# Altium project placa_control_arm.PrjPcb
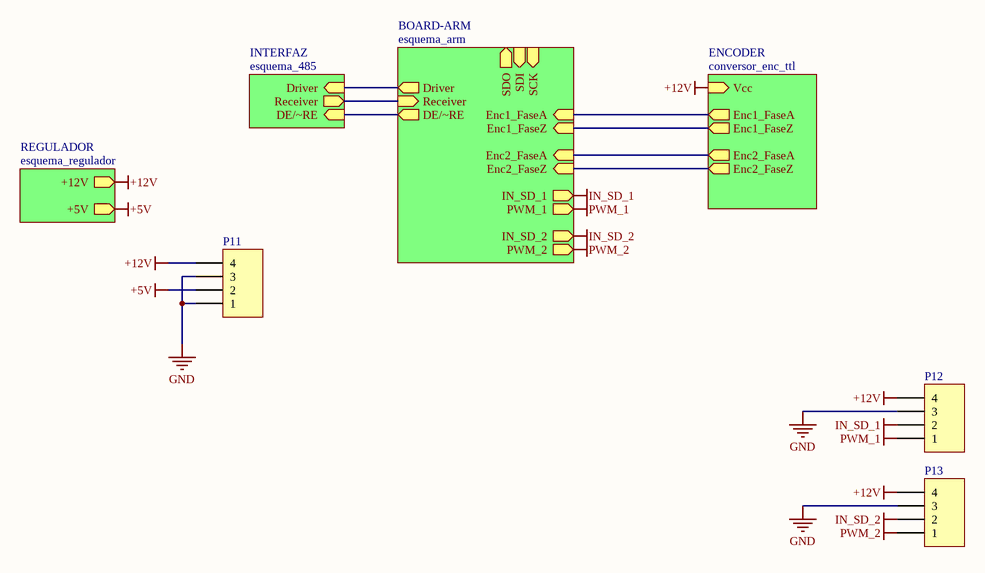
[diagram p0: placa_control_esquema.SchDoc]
5 sheets, 40 parts. Net scope: hierarchical (ports join the sheet entries above them; power ports are global).
Board file: placa_control_impresion.PcbDoc
Sheets:
  placa_control_esquema.SchDoc
    REGULADOR = esquema_regulador.SchDoc
    INTERFAZ = esquema_485.SchDoc
    BOARD-ARM = esquema_arm.SchDoc
    ENCODER = conversor_enc_ttl.SchDoc

## Sheet placa_control_esquema.SchDoc
size A4

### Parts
P11  Header 4  [HDR1X5]  (value not drawn)
P12  Header 4  [HDR1X5]  (value not drawn)
P13  Header 4  [HDR1X5]  (value not drawn)

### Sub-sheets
BOARD-ARM = esquema_arm: SDI (in), SDO (out), SCK (in), Enc1_FaseA (in), Enc1_FaseZ (in), Enc2_FaseA (in), Enc2_FaseZ (in), DE/~RE (out), Receiver (in), Driver (out), PWM_1 (out), PWM_2 (out), IN_SD_2 (out), IN_SD_1 (out)
ENCODER = conversor_enc_ttl: Enc1_FaseA (out), Enc1_FaseZ (out), Enc2_FaseA (out), Enc2_FaseZ (out), Vcc (in)
INTERFAZ = esquema_485: Driver (in), Receiver (out), DE/~RE (in)
REGULADOR = esquema_regulador: +12V (out), +5V (out)

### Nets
+5V: P11.2 ; sheet REGULADOR/+5V
+12V: P11.4 P12.4 P13.4 ; sheet REGULADOR/+12V, sheet ENCODER/Vcc
Enc1_FaseZ: sheet BOARD-ARM/Enc1_FaseZ, sheet ENCODER/Enc1_FaseZ
Enc2_FaseZ: sheet BOARD-ARM/Enc2_FaseZ, sheet ENCODER/Enc2_FaseZ
GND: P11.1 P11.3 P12.3 P13.3
IN_SD_1: P12.2 ; sheet BOARD-ARM/IN_SD_1
IN_SD_2: P13.2 ; sheet BOARD-ARM/IN_SD_2
PWM_1: P12.1 ; sheet BOARD-ARM/PWM_1
PWM_2: P13.1 ; sheet BOARD-ARM/PWM_2
D/~E: sheet INTERFAZ/DE/~RE, sheet BOARD-ARM/DE/~RE
DRIVER: sheet INTERFAZ/Driver, sheet BOARD-ARM/Driver
RECIEVER: sheet INTERFAZ/Receiver, sheet BOARD-ARM/Receiver
NetP3_21: sheet BOARD-ARM/Enc2_FaseA, sheet ENCODER/Enc2_FaseA
NetP4_14: sheet BOARD-ARM/Enc1_FaseA, sheet ENCODER/Enc1_FaseA

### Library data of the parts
P11-P13 = Header 4: Header, 4-Pin; value: hdr1x5

## Sheet esquema_regulador.SchDoc
size A4
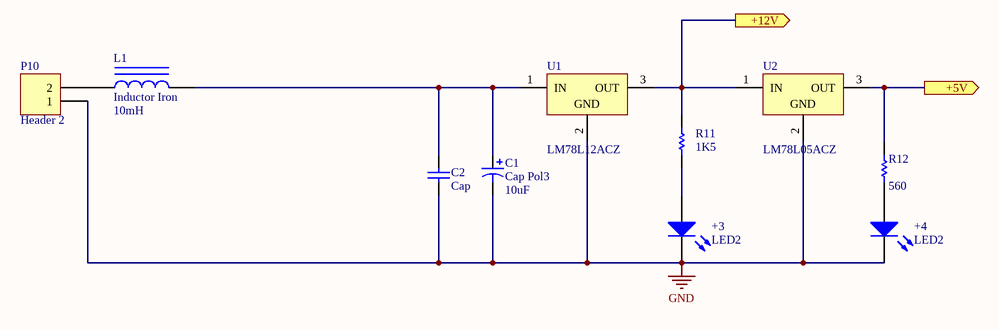
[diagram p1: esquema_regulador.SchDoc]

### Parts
+3  LED2  [CAPPR2.5-6.3X5]
+4  LED2  [CAPPR2.5-6.3X5]
C1  Cap Pol3  value 10uF  [CAPPR3.5-8X15]
C2  Cap  [RAD-0.1]
L1  Inductor Iron  value 10mH  [bobina_Choque]
P10  Header 2  [pwheader1x2]
R11  value 1K5  [AXIAL-0.3]  (hidden comment: Carbon 1/8w 5%)
R12  value 560  [AXIAL-0.3]  (hidden comment: Carbon 1/8w 5%)
U1  LM78L12ACZ  [T03B]
U2  LM78L05ACZ  [T03B]

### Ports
+5V (out), +12V (out)

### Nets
+5V: R12.2 U2.3(OUT) ; port +5V
+12V: R11.2 U1.3(OUT) U2.1(IN) ; port +12V
GND: +3.2(K) +4.2(K) C1.2 C2.1 P10.1 U1.2(GND) U2.2(GND)
Net+3_1: +3.1(A) R11.1
Net+4_1: +4.1(A) R12.1
NetC1_1: C1.1 C2.2 L1.2 U1.1(IN)
NetL1_1: L1.1 P10.2

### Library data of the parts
+3 +4 = LED2: Typical RED, GREEN, YELLOW, AMBER GaAs LED
C1 = Cap Pol3: Polarized Capacitor 35V
C2 = Cap: Capacitor
L1 = Inductor Iron: Magnetic-Core Inductor
P10 = Header 2: Header, 2-Pin
R11 R12 = Res Semi: Semiconductor Resistor
U1 = LM78L12ACZ: 3-Terminal Positive Regulator; PackageDocument: 2000
U2 = LM78L05ACZ: 3-Terminal Positive Regulator; PackageDocument: 2000

## Sheet esquema_485.SchDoc
size A4
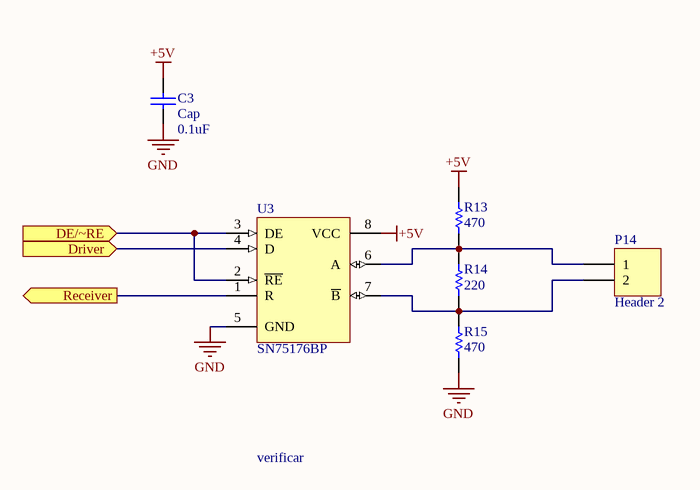
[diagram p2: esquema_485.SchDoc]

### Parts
C3  Cap  value 0.1uF  [CAPPR2.5-6.3X5]
P14  Header 2  [wf2s]
R13  value 470  [AXIAL-0.3]  (hidden comment: Carbon 1/8w 5%)
R14  value 220  [AXIAL-0.3]  (hidden comment: Carbon 1/8w 5%)
R15  value 470  [AXIAL-0.3]  (hidden comment: Carbon 1/8w 5%)
U3  SN75176BP  [626-05]

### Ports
DE/~RE (in), Driver (in), Receiver (out)

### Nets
+5V: C3.2 R13.2 U3.8(VCC)
GND: C3.1 R15.1 U3.5(GND)
D/~E: U3.2(~{RE}) U3.3(DE) ; port DE/~RE
DRIVER: U3.4(D) ; port Driver
RECIEVER: U3.1(R) ; port Receiver
NetP14_1: P14.1 R13.1 R14.2 U3.6(A)
NetP14_2: P14.2 R14.1 R15.2 U3.7(~{B})

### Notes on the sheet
- verificar

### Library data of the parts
C3 = Cap: Capacitor
P14 = Header 2: Header, 2-Pin
R13-R15 = Res Semi: Semiconductor Resistor
U3 = SN75176BP: Differential Bus Transceiver; Note: Receiver Hysteresis of 50mV Typical

## Sheet esquema_arm.SchDoc
size A4
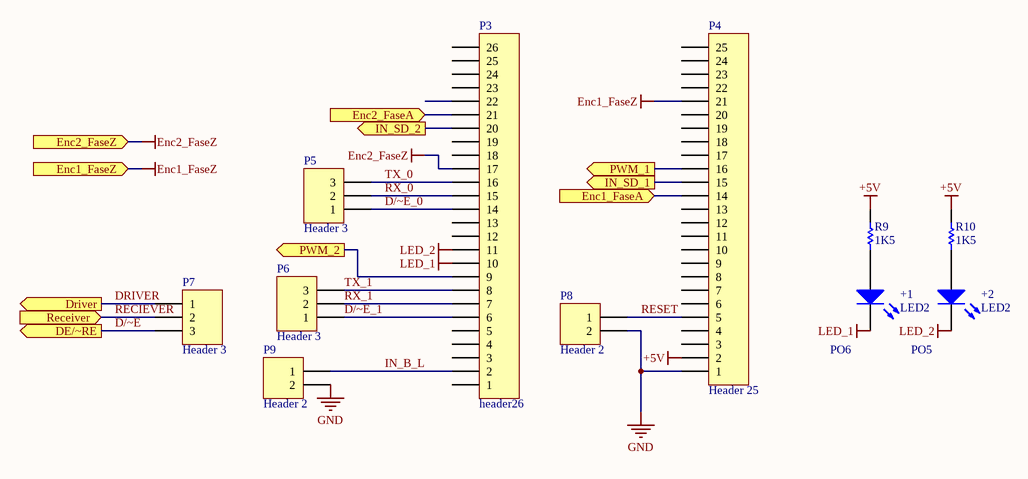
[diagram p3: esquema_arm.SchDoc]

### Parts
+1  LED2  [CAPPR2.5-6.3X5]
+2  LED2  [CAPPR2.5-6.3X5]
P3  header26  [HDR1x26]
P4  Header 25  [HDR1X25]
P5  Header 3  [HDR1X3]
P6  Header 3  [HDR1X3]
P7  Header 3  [HDR1X3]
P8  Header 2  [wf2s]
P9  Header 2  [wf2s]
R9  value 1K5  [AXIAL-0.3]  (hidden comment: Carbon 1/8w 5%)
R10  value 1K5  [AXIAL-0.3]  (hidden comment: Carbon 1/8w 5%)

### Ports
DE/~RE (out), Driver (out), Enc1_FaseA (in), Enc1_FaseZ (in), Enc2_FaseA (in), Enc2_FaseZ (in), IN_SD_1 (out), IN_SD_2 (out), PWM_1 (out), PWM_2 (out), Receiver (in)

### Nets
+5V: P4.2 R9.1 R10.1
Enc1_FaseZ: P4.21 ; port Enc1_FaseZ
Enc2_FaseZ: P3.17 ; port Enc2_FaseZ
GND: P4.1 P8.2 P9.2
IN_SD_1: P4.15 ; port IN_SD_1
IN_SD_2: P3.20 ; port IN_SD_2
LED_1: +1.2(K) P3.10
LED_2: +2.2(K) P3.11
PWM_1: P4.16 ; port PWM_1
PWM_2: P3.9 ; port PWM_2
D/~E: P7.3 ; port DE/~RE
D/~E_0: P3.14 P5.1
D/~E_1: P3.6 P6.1
DRIVER: P7.1 ; port Driver
IN_B_L: P3.2 P9.1
RECIEVER: P7.2 ; port Receiver
RESET: P4.5 P8.1
RX_0: P3.15 P5.2
RX_1: P3.7 P6.2
TX_0: P3.16 P5.3
TX_1: P3.8 P6.3
Net+1_1: +1.1(A) R9.2
Net+2_1: +2.1(A) R10.2
NetP3_21: P3.21 ; port Enc2_FaseA
NetP4_14: P4.14 ; port Enc1_FaseA

Not connected (* = marked no-connect by the designer): P3 1 3 4 5 12 13 18 19 22 23 24 25 26; P4 3 4 6 7 8 9 10 11 12 13 17 18 19 20 22 23 24 25

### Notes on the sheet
- (near +1) PO6
- PO5

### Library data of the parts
+1 +2 = LED2: as +3 on sheet esquema_regulador
P3 = Component_1
P4 = Header 25: Header, 25-Pin
P5-P7 = Header 3: Header, 3-Pin
P8 P9 = Header 2: Header, 2-Pin
R9 R10 = Res Semi: Semiconductor Resistor

## Sheet conversor_enc_ttl.SchDoc
size A4
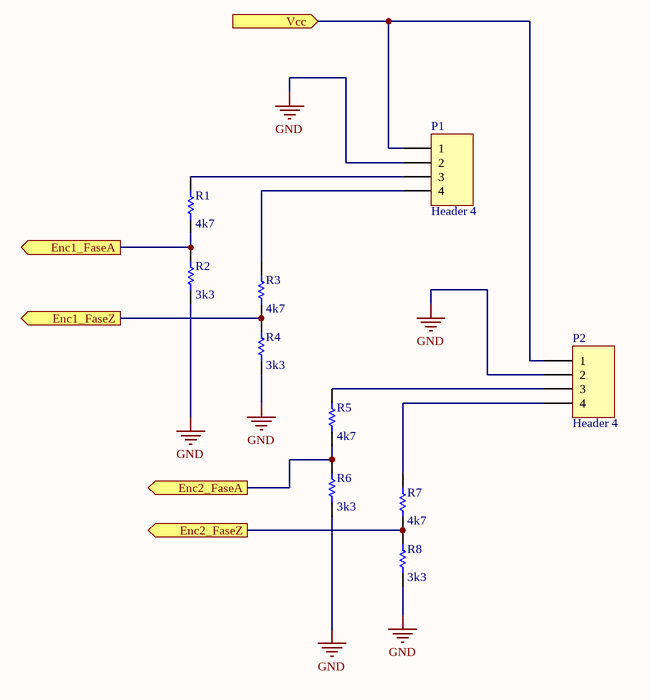
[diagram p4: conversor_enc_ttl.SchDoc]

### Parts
P1  Header 4  [HDR1X5]
P2  Header 4  [HDR1X5]
R1  value 4k7  [AXIAL-0.3]  (hidden comment: metal film 2%)
R2  value 3k3  [AXIAL-0.3]  (hidden comment: metal film 2%)
R3  value 4k7  [AXIAL-0.3]  (hidden comment: metal film 2%)
R4  value 3k3  [AXIAL-0.3]  (hidden comment: metal film 2%)
R5  value 4k7  [AXIAL-0.3]  (hidden comment: metal film 2%)
R6  value 3k3  [AXIAL-0.3]  (hidden comment: metal film 2%)
R7  value 4k7  [AXIAL-0.3]  (hidden comment: metal film 2%)
R8  value 3k3  [AXIAL-0.3]  (hidden comment: metal film 2%)

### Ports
Enc1_FaseA (out), Enc1_FaseZ (out), Enc2_FaseA (out), Enc2_FaseZ (out), Vcc (in)

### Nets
+12V: P1.1 P2.1 ; port Vcc
Enc1_FaseZ: R3.1 R4.2 ; port Enc1_FaseZ
Enc2_FaseZ: R7.1 R8.2 ; port Enc2_FaseZ
GND: P1.2 P2.2 R2.1 R4.1 R6.1 R8.1
NetP1_3: P1.3 R1.2
NetP1_4: P1.4 R3.2
NetP2_3: P2.3 R5.2
NetP2_4: P2.4 R7.2
NetP3_21: R5.1 R6.2 ; port Enc2_FaseA
NetP4_14: R1.1 R2.2 ; port Enc1_FaseA

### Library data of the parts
P1 P2 = Header 4: Header, 4-Pin
R1-R8 = Res Semi: Semiconductor Resistor

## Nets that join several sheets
+5V: placa_control_esquema (P11.2), esquema_regulador (R12.2 U2.3), esquema_485 (C3.2 R13.2 U3.8), esquema_arm (P4.2 R9.1 R10.1)
+12V: placa_control_esquema (P11.4 P12.4 P13.4), esquema_regulador (R11.2 U1.3 U2.1), conversor_enc_ttl (P1.1 P2.1)
Enc1_FaseZ: esquema_arm (P4.21), conversor_enc_ttl (R3.1 R4.2)
Enc2_FaseZ: esquema_arm (P3.17), conversor_enc_ttl (R7.1 R8.2)
GND: placa_control_esquema (P11.1 P11.3 P12.3 P13.3), esquema_regulador (7 pins), esquema_485 (C3.1 R15.1 U3.5), esquema_arm (P4.1 P8.2 P9.2), conversor_enc_ttl (6 pins)
IN_SD_1: placa_control_esquema (P12.2), esquema_arm (P4.15)
IN_SD_2: placa_control_esquema (P13.2), esquema_arm (P3.20)
PWM_1: placa_control_esquema (P12.1), esquema_arm (P4.16)
PWM_2: placa_control_esquema (P13.1), esquema_arm (P3.9)
D/~E: esquema_485 (U3.2 U3.3), esquema_arm (P7.3)
DRIVER: esquema_485 (U3.4), esquema_arm (P7.1)
NetP3_21: esquema_arm (P3.21), conversor_enc_ttl (R5.1 R6.2)
NetP4_14: esquema_arm (P4.14), conversor_enc_ttl (R1.1 R2.2)
RECIEVER: esquema_485 (U3.1), esquema_arm (P7.2)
